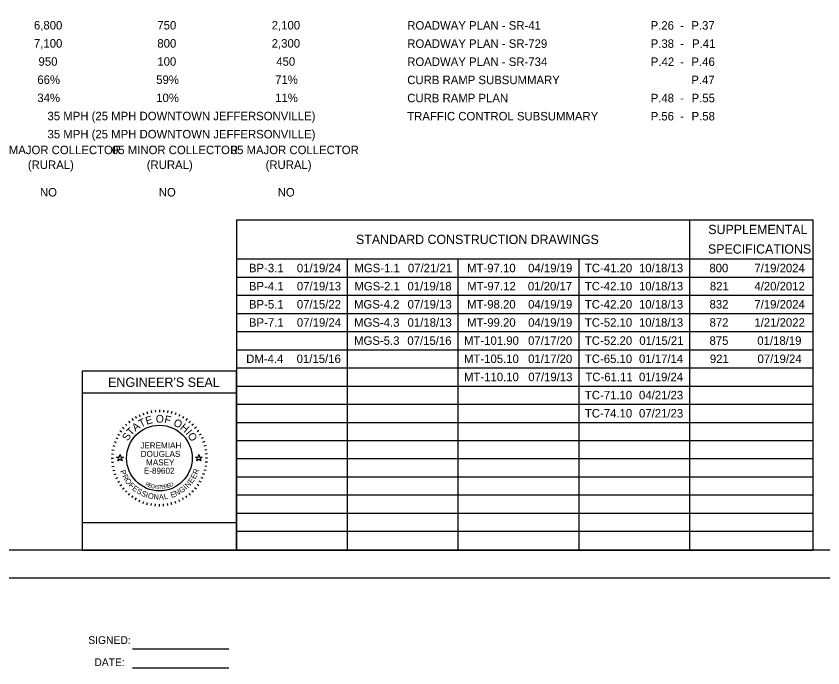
# Model space of a CAD drawing. Extents: x 0 to 34, y -1.6 to 22.
# Drawn here: x 7.84 to 22.48, y -1.63 to 10.19 of the extents above; entities that cross this region are included whole.
import ezdxf

# ---------------------------------------------------------------- set-up
doc = ezdxf.new("R2010")
doc.units = 0
for name, color, linetype in [('SH_Border', 7, 'Continuous'), ('SH_Cut_Line', 7, 'Continuous'), ('SH_Data', 7, 'Continuous'), ('SH_Text', 7, 'Continuous')]:
    doc.layers.add(name, color=color, linetype=linetype)

msp = doc.modelspace()

# ---------------------------------------------------------------- linework, layer by layer
at = {"layer": 'SH_Border'}
msp.add_lwpolyline([(1.5, 21.5), (33.5, 21.5), (33.5, 0.5), (1.5, 0.5)], close=True, dxfattribs=at)
at = {"layer": 'SH_Cut_Line'}
msp.add_lwpolyline([(0, 0), (34, 0), (34, 22), (0, 22)], close=True, dxfattribs=at)
at = {"layer": 'SH_Data'}
for p, q in [((11.844, 3.75), (9.044, 3.75)), ((9.044, 3.75), (9.044, 0.5)), ((11.844, 0.5), (11.844, 3.75)), ((11.844, 3.35), (9.044, 3.35)), ((10.007, 2.931), (10.027, 2.896)), ((10.075, 2.966), (10.091, 2.93)), ((10.145, 2.995), (10.159, 2.957)), ((10.218, 3.018), (10.228, 2.979)), ((10.292, 3.034), (10.299, 2.995)), ((10.368, 3.044), (10.372, 3.005)), ((10.444, 3.048), (10.444, 3.008)), ((10.521, 3.044), (10.517, 3.005)), ((10.596, 3.034), (10.589, 2.995)), ((10.671, 3.018), (10.66, 2.979)), ((10.744, 2.995), (10.73, 2.957)), ((10.814, 2.966), (10.797, 2.93)), ((10.882, 2.931), (10.862, 2.896)), ((9.826, 2.792), (9.854, 2.763)), ((9.882, 2.843), (9.908, 2.812)), ((9.942, 2.89), (9.965, 2.857)), ((10.946, 2.89), (10.923, 2.857)), ((11.007, 2.843), (10.981, 2.812)), ((11.063, 2.792), (11.035, 2.763)), ((9.728, 2.675), (9.76, 2.652)), ((9.774, 2.735), (9.805, 2.71)), ((11.115, 2.735), (11.084, 2.71)), ((11.161, 2.675), (11.128, 2.652)), ((9.651, 2.543), (9.688, 2.526)), ((9.687, 2.61), (9.721, 2.59)), ((11.202, 2.61), (11.168, 2.59)), ((11.237, 2.543), (11.201, 2.526)), ((9.599, 2.399), (9.638, 2.389)), ((9.622, 2.472), (9.66, 2.458)), ((11.267, 2.472), (11.229, 2.458)), ((11.29, 2.399), (11.251, 2.389)), ((9.573, 2.249), (9.613, 2.246)), ((9.583, 2.325), (9.622, 2.318)), ((11.306, 2.325), (11.267, 2.318)), ((11.316, 2.249), (11.276, 2.246)), ((9.569, 2.173), (9.609, 2.173)), ((9.573, 2.097), (9.613, 2.1)), ((11.316, 2.097), (11.276, 2.1)), ((11.319, 2.173), (11.279, 2.173)), ((9.583, 2.021), (9.622, 2.028)), ((9.599, 1.946), (9.638, 1.957)), ((11.29, 1.946), (11.251, 1.957)), ((11.306, 2.021), (11.267, 2.028)), ((9.622, 1.874), (9.66, 1.887)), ((9.651, 1.803), (9.688, 1.82)), ((11.237, 1.803), (11.201, 1.82)), ((11.267, 1.874), (11.229, 1.887)), ((9.687, 1.735), (9.721, 1.755)), ((9.728, 1.671), (9.76, 1.694)), ((9.774, 1.61), (9.805, 1.636)), ((11.115, 1.61), (11.084, 1.636)), ((11.161, 1.671), (11.128, 1.694)), ((11.202, 1.735), (11.168, 1.755)), ((9.826, 1.554), (9.854, 1.582)), ((9.882, 1.503), (9.908, 1.533)), ((9.942, 1.456), (9.965, 1.489)), ((10.946, 1.456), (10.923, 1.489)), ((11.007, 1.503), (10.981, 1.533)), ((11.063, 1.554), (11.035, 1.582)), ((10.007, 1.415), (10.027, 1.45)), ((10.075, 1.38), (10.091, 1.416)), ((10.145, 1.351), (10.159, 1.388)), ((10.218, 1.328), (10.228, 1.366)), ((10.292, 1.311), (10.299, 1.35)), ((10.368, 1.301), (10.372, 1.341)), ((10.444, 1.298), (10.444, 1.338)), ((10.521, 1.301), (10.517, 1.341)), ((10.596, 1.311), (10.589, 1.35)), ((10.671, 1.328), (10.66, 1.366)), ((10.744, 1.351), (10.73, 1.388)), ((10.814, 1.38), (10.797, 1.416)), ((10.882, 1.415), (10.862, 1.45)), ((11.844, 0.5), (9.044, 0.5))]:
    msp.add_line(p, q, dxfattribs=at)
msp.add_lwpolyline([(11.844, 0.5), (11.844, 1), (9.044, 1), (9.044, 0.5)], close=True, dxfattribs=at)
msp.add_circle((10.444, 2.173), 0.595, dxfattribs=at)
at = {"layer": 'SH_Text'}
for p, q in [((11.844, 6.495), (22.303, 6.495)), ((11.844, 6.495), (11.844, 0.5)), ((20.063, 6.495), (20.063, 0.5)), ((22.303, 6.495), (22.303, 0.5)), ((11.844, 5.787), (22.303, 5.787)), ((13.854, 5.787), (13.854, 0.5)), ((15.863, 5.787), (15.863, 0.5)), ((18.054, 5.787), (18.054, 0.5)), ((11.844, 5.458), (22.303, 5.458)), ((11.844, 5.128), (22.303, 5.128)), ((11.844, 4.799), (22.303, 4.799)), ((11.844, 4.469), (22.303, 4.469)), ((11.844, 4.14), (22.303, 4.14)), ((11.844, 3.811), (22.303, 3.811)), ((11.844, 3.481), (22.303, 3.481)), ((11.844, 3.152), (22.303, 3.152)), ((11.844, 2.822), (22.303, 2.822)), ((11.844, 2.493), (22.303, 2.493)), ((11.844, 2.164), (22.303, 2.164)), ((11.844, 1.834), (22.303, 1.834)), ((11.844, 1.505), (22.303, 1.505)), ((11.844, 1.175), (22.303, 1.175)), ((11.844, 0.846), (22.303, 0.846)), ((11.844, 0.5), (22.303, 0.5)), ((9.955, -1.286), (11.705, -1.286)), ((9.955, -1.633), (11.705, -1.633))]:
    msp.add_line(p, q, dxfattribs=at)
for points in [[(9.668, 2.193), (9.715, 2.193), (9.729, 2.237), (9.744, 2.193), (9.791, 2.193), (9.753, 2.165), (9.767, 2.121), (9.729, 2.148), (9.691, 2.121), (9.706, 2.165)], [(11.098, 2.193), (11.145, 2.193), (11.159, 2.237), (11.174, 2.193), (11.221, 2.193), (11.183, 2.165), (11.197, 2.121), (11.159, 2.148), (11.121, 2.121), (11.136, 2.165)]]:
    msp.add_lwpolyline(points, close=True, dxfattribs=at)

# ---------------------------------------------------------------- texts
at = {"layer": 'SH_Data'}
for s, height, p in [("ENGINEER'S SEAL", 0.17, (9.512, 3.465)), ('JEREMIAH', 0.11, (10.098, 2.348)), ('DOUGLAS', 0.11, (10.105, 2.194)), ('MASEY', 0.11, (10.202, 2.041)), ('E-89602', 0.11, (10.162, 1.888))]:
    msp.add_text(s, height=height, dxfattribs=at).set_placement(p)
for s, height, rotation, p in [('E', 0.14, 15.7571, (10.213, 2.777)), ('O', 0.14, 359.7812, (10.379, 2.817)), ('F', 0.14, 347.4362, (10.525, 2.815)), ('A', 0.14, 36.4747, (10.008, 2.651)), ('T', 0.14, 25.7167, (10.106, 2.725)), ('O', 0.14, 332.2586, (10.684, 2.774)), ('H', 0.14, 319.9136, (10.808, 2.709)), ('T', 0.14, 46.4344, (9.933, 2.569)), ('I', 0.14, 308.367, (10.911, 2.621)), ('S', 0.14, 57.1924, (9.872, 2.474)), ('O', 0.14, 303.1491, (10.947, 2.582)), ('P', 0.1, 291.494, (9.727, 1.935)), ('R', 0.1, 69.2322, (11.136, 1.868)), ('R', 0.1, 298.7311, (9.763, 1.844)), ('O', 0.1, 306.4666, (9.81, 1.761)), ('E', 0.1, 54.758, (11.038, 1.704)), ('E', 0.1, 61.9951, (11.092, 1.783)), ('F', 0.1, 314.7068, (9.879, 1.671)), ('E', 0.1, 321.4393, (9.942, 1.608)), ('S', 0.1, 328.6764, (10.019, 1.548)), ('R', 0.07, 334.487, (10.182, 1.678)), ('E', 0.07, 341.04, (10.235, 1.653)), ('G', 0.07, 347.4752, (10.286, 1.635)), ('I', 0.07, 353.7858, (10.353, 1.62)), ('S', 0.07, 356.8926, (10.38, 1.616)), ('T', 0.07, 3.0061, (10.43, 1.611)), ('E', 0.07, 6.0117, (10.483, 1.614)), ('R', 0.07, 11.9184, (10.537, 1.62)), ('E', 0.07, 17.6836, (10.594, 1.633)), ('D', 0.07, 23.3052, (10.645, 1.65)), ('G', 0.1, 35.0469, (10.842, 1.53)), ('I', 0.1, 43.287, (10.931, 1.594)), ('N', 0.1, 47.0224, (10.965, 1.624)), ('S', 0.1, 335.9134, (10.101, 1.499)), ('I', 0.1, 343.1505, (10.185, 1.462)), ('O', 0.1, 346.8859, (10.228, 1.448)), ('N', 0.1, 355.1261, (10.333, 1.425)), ('A', 0.1, 2.8617, (10.437, 1.416)), ('L', 0.1, 10.0987, (10.534, 1.422)), ('E', 0.1, 20.0742, (10.666, 1.45)), ('N', 0.1, 27.3113, (10.749, 1.48))]:
    msp.add_text(s, height=height, rotation=rotation, dxfattribs=at).set_placement(p)
at = {"layer": 'SH_Text'}
for s, height, p in [('6,800', 0.154, (8.167, 9.95)), ('750', 0.154, (10.407, 9.95)), ('2,100', 0.154, (12.482, 9.95)), ('ROADWAY PLAN - SR-41', 0.154, (14.942, 9.947)), ('P.26', 0.154, (19.359, 9.947)), ('P.37', 0.154, (20.098, 9.947)), ('-', 0.154, (19.895, 9.947)), ('7,100', 0.154, (8.167, 9.621)), ('800', 0.154, (10.407, 9.621)), ('2,300', 0.154, (12.482, 9.621)), ('ROADWAY PLAN - SR-729', 0.154, (14.942, 9.617)), ('P.38', 0.154, (19.36, 9.617)), ('-', 0.154, (19.895, 9.617)), ('P.41', 0.154, (20.111, 9.617)), ('950', 0.154, (8.25, 9.292)), ('100', 0.154, (10.407, 9.292)), ('450', 0.154, (12.565, 9.292)), ('ROADWAY PLAN - SR-734', 0.154, (14.942, 9.288)), ('P.42', 0.154, (19.363, 9.288)), ('P.46', 0.154, (20.1, 9.288)), ('-', 0.154, (19.895, 9.288)), ('66%', 0.154, (8.229, 8.962)), ('59%', 0.154, (10.386, 8.962)), ('71%', 0.154, (12.544, 8.962)), ('CURB RAMP SUBSUMMARY', 0.154, (14.942, 8.958)), ('P.47', 0.154, (20.098, 8.958)), ('34%', 0.154, (8.229, 8.633)), ('10%', 0.154, (10.386, 8.633)), ('11%', 0.154, (12.544, 8.633)), ('CURB RAMP PLAN', 0.154, (14.942, 8.629)), ('P.48', 0.154, (19.36, 8.629)), ('-', 0.154, (19.895, 8.629)), ('P.55', 0.154, (20.103, 8.629)), ('35 MPH (25 MPH DOWNTOWN JEFFERSONVILLE)', 0.154, (8.413, 8.303)), ('TRAFFIC CONTROL SUBSUMMARY', 0.154, (14.942, 8.3)), ('P.56', 0.154, (19.359, 8.3)), ('-', 0.154, (19.895, 8.3)), ('P.58', 0.154, (20.102, 8.3)), ('35 MPH (25 MPH DOWNTOWN JEFFERSONVILLE)', 0.154, (8.413, 7.974)), ('05 MAJOR COLLECTOR ', 0.154, (7.425, 7.688)), ('05 MINOR COLLECTOR ', 0.154, (9.584, 7.688)), ('05 MAJOR COLLECTOR ', 0.154, (11.74, 7.688)), ('(RURAL)', 0.154, (8.056, 7.419)), ('(RURAL)', 0.154, (10.214, 7.419)), ('(RURAL)', 0.154, (12.371, 7.419)), ('NO', 0.154, (8.276, 6.92)), ('NO', 0.154, (10.433, 6.92)), ('NO', 0.154, (12.591, 6.92)), ('SUPPLEMENTAL', 0.168, (20.406, 6.238)), ('STANDARD CONSTRUCTION DRAWINGS', 0.168, (14.012, 6.057)), ('SPECIFICATIONS', 0.168, (20.4, 5.884)), ('BP-3.1', 0.154, (12.069, 5.545)), ('01/19/24', 0.154, (12.939, 5.545)), ('MGS-1.1', 0.154, (13.983, 5.545)), ('07/21/21', 0.154, (14.954, 5.545)), ('MT-97.10', 0.154, (16.028, 5.545)), ('04/19/19', 0.154, (17.136, 5.545)), ('TC-41.20', 0.154, (18.166, 5.545)), ('10/18/13', 0.154, (19.148, 5.545)), ('800', 0.154, (20.425, 5.545)), ('7/19/2024', 0.154, (21.242, 5.545)), ('BP-4.1', 0.154, (12.069, 5.216)), ('07/19/13', 0.154, (12.939, 5.216)), ('MGS-2.1', 0.154, (13.983, 5.216)), ('01/19/18', 0.154, (14.945, 5.216)), ('MT-97.12', 0.154, (16.031, 5.216)), ('01/20/17', 0.154, (17.132, 5.216)), ('TC-42.10', 0.154, (18.166, 5.216)), ('10/18/13', 0.154, (19.148, 5.216)), ('821', 0.154, (20.434, 5.216)), ('4/20/2012', 0.154, (21.242, 5.216)), ('BP-5.1', 0.154, (12.069, 4.887)), ('07/15/22', 0.154, (12.938, 4.887)), ('MGS-4.2', 0.154, (13.976, 4.887)), ('07/19/13', 0.154, (14.948, 4.887)), ('MT-98.20', 0.154, (16.028, 4.887)), ('04/19/19', 0.154, (17.136, 4.887)), ('TC-42.20', 0.154, (18.166, 4.887)), ('10/18/13', 0.154, (19.148, 4.887)), ('832', 0.154, (20.428, 4.887)), ('7/19/2024', 0.154, (21.242, 4.887)), ('BP-7.1', 0.154, (12.069, 4.557)), ('07/19/24', 0.154, (12.939, 4.557)), ('MGS-4.3', 0.154, (13.977, 4.557)), ('01/18/13', 0.154, (14.948, 4.557)), ('MT-99.20', 0.154, (16.028, 4.557)), ('04/19/19', 0.154, (17.136, 4.557)), ('TC-52.10', 0.154, (18.166, 4.557)), ('10/18/13', 0.154, (19.148, 4.557)), ('872', 0.154, (20.428, 4.557)), ('1/21/2022', 0.154, (21.242, 4.557)), ('MGS-5.3', 0.154, (13.977, 4.228)), ('07/15/16', 0.154, (14.944, 4.228)), ('MT-101.90', 0.154, (15.972, 4.228)), ('07/17/20', 0.154, (17.135, 4.228)), ('TC-52.20', 0.154, (18.166, 4.228)), ('01/15/21', 0.154, (19.154, 4.228)), ('875', 0.154, (20.427, 4.228)), ('01/18/19', 0.154, (21.295, 4.228)), ('DM-4.4', 0.154, (12.019, 3.898)), ('01/15/16', 0.154, (12.935, 3.898)), ('MT-105.10', 0.154, (15.972, 3.898)), ('01/17/20', 0.154, (17.135, 3.898)), ('TC-65.10', 0.154, (18.166, 3.898)), ('01/17/14', 0.154, (19.148, 3.898)), ('921', 0.154, (20.434, 3.898)), ('07/19/24', 0.154, (21.298, 3.898)), ('MT-110.10', 0.154, (15.972, 3.569)), ('07/19/13', 0.154, (17.139, 3.569)), ('TC-61.11', 0.154, (18.175, 3.569)), ('01/19/24', 0.154, (19.148, 3.569)), ('TC-71.10', 0.154, (18.166, 3.239)), ('04/21/23', 0.154, (19.148, 3.239)), ('TC-74.10', 0.154, (18.166, 2.91)), ('07/21/23', 0.154, (19.148, 2.91)), ('SIGNED:', 0.14, (9.153, -1.199)), ('DATE:', 0.14, (9.264, -1.6))]:
    msp.add_text(s, height=height, dxfattribs=at).set_placement(p)

doc.saveas('drawing.dxf')
